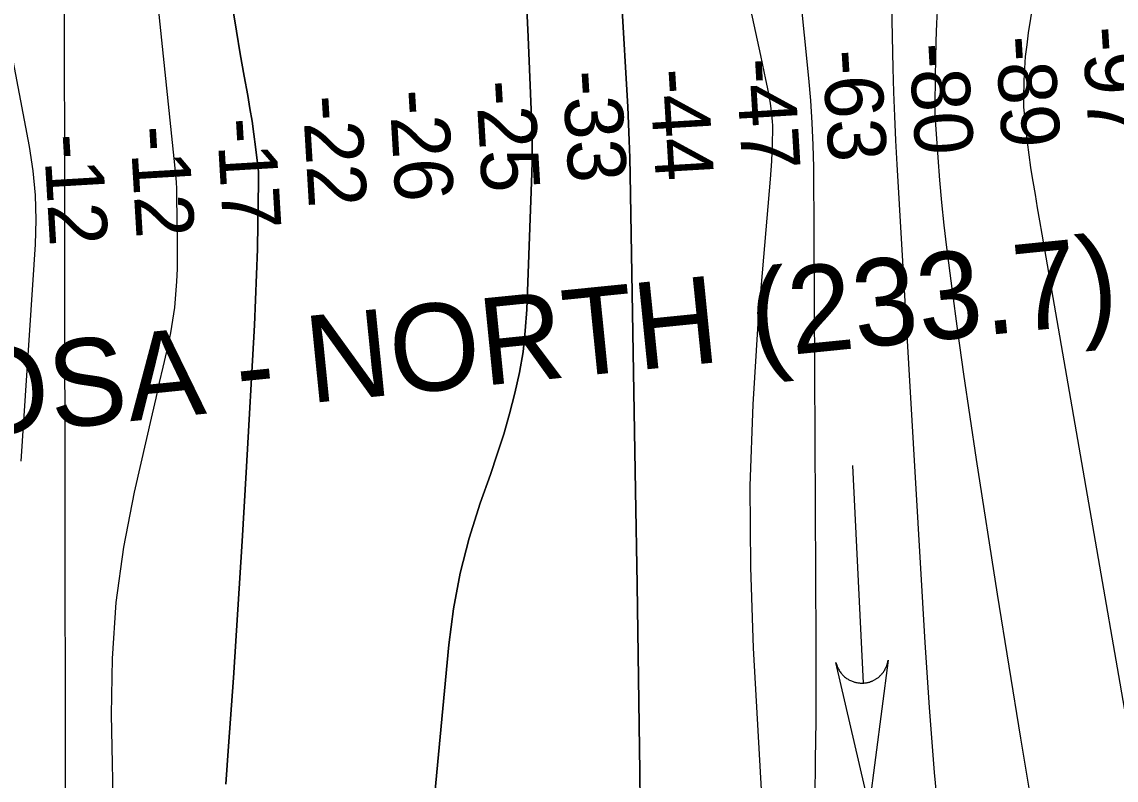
# Model space of a CAD drawing. Extents: x 3313442 to 3351311, y 721974 to 747360.
# Drawn here: x 3322775 to 3324032, y 728448 to 729320 of the extents above; entities that cross this region are included whole.
import ezdxf

# ---------------------------------------------------------------- set-up
doc = ezdxf.new("R2010")
doc.units = 0
for name, color, linetype in [('V-CHAN-NAID', 7, 'Continuous'), ('V-GRID-MAJR', 7, 'Continuous'), ('V-RIVR-RANG', 7, 'Continuous'), ('V-STRM-FLOW', 7, 'Continuous'), ('V-TOPO-DPTH', 7, 'Continuous'), ('V-TOPO-MAJR', 7, 'Continuous'), ('V-TOPO-MINR', 7, 'Continuous')]:
    doc.layers.add(name, color=color, linetype=linetype)

msp = doc.modelspace()

# ---------------------------------------------------------------- linework, layer by layer
at = {"layer": 'V-GRID-MAJR'}
msp.add_spline([(3322826, 727358.6), (3322818.9, 733418.5), (3322811.9, 739480.2), (3322804.8, 745542), (3322804.8, 745543.9)], degree=3, dxfattribs=at)
at = {"layer": 'V-STRM-FLOW'}
msp.add_line((3323729.4, 728810.1), (3323741.5, 728560), dxfattribs=at)
msp.add_lwpolyline([(3323770.2, 728586.4), (3323748.3, 728418.5), (3323710.3, 728583.5), (3323711.2, 728580.6), (3323712.2, 728577.8), (3323712.8, 728576.8), (3323713.2, 728575.8), (3323713.9, 728574.7), (3323714.5, 728573.7), (3323715.1, 728572.8), (3323716, 728571.7), (3323717, 728570.5), (3323717.5, 728569.8), (3323718.3, 728569), (3323719.4, 728568), (3323720.2, 728567.2), (3323721.2, 728566.4), (3323721.8, 728565.9), (3323722.5, 728565.4), (3323723.5, 728564.8), (3323724.3, 728564.3), (3323725.2, 728563.8), (3323725.9, 728563.4), (3323727, 728562.8), (3323728.1, 728562.4), (3323728.9, 728562), (3323730, 728561.6), (3323730.9, 728561.3), (3323731.7, 728561.1), (3323732.3, 728560.9), (3323733.3, 728560.7), (3323734.3, 728560.5), (3323735.3, 728560.3), (3323736.2, 728560.2), (3323737.2, 728560.1), (3323738.2, 728560), (3323739, 728559.9), (3323740.2, 728559.9), (3323741.5, 728560), (3323741.9, 728560), (3323742.5, 728560), (3323743.3, 728560.1), (3323744, 728560.2), (3323744.6, 728560.3), (3323745.3, 728560.4), (3323746.1, 728560.5), (3323746.6, 728560.6), (3323747.4, 728560.8), (3323748.2, 728561), (3323748.7, 728561.2), (3323749.9, 728561.6), (3323750.6, 728561.8), (3323751.1, 728562), (3323751.8, 728562.3), (3323752.5, 728562.6), (3323753.2, 728562.9), (3323754, 728563.3), (3323754.7, 728563.7), (3323755.3, 728564), (3323755.8, 728564.3), (3323756.4, 728564.7), (3323757, 728565.1), (3323757.7, 728565.5), (3323758.3, 728566), (3323759, 728566.5), (3323759.8, 728567.2), (3323760.3, 728567.7), (3323760.9, 728568.2), (3323761.5, 728568.8), (3323762, 728569.2), (3323762.4, 728569.7), (3323763.1, 728570.5), (3323763.2, 728570.6), (3323763.6, 728571), (3323763.9, 728571.4), (3323764.3, 728571.9), (3323764.8, 728572.6), (3323765.2, 728573.2), (3323765.5, 728573.7), (3323765.9, 728574.4), (3323766.3, 728575), (3323766.6, 728575.5), (3323766.9, 728576.1), (3323767.4, 728577), (3323767.6, 728577.5), (3323767.8, 728577.9), (3323768, 728578.3), (3323768.2, 728578.7), (3323768.4, 728579.3), (3323768.7, 728580), (3323768.9, 728580.6), (3323769.1, 728581.2), (3323769.3, 728582), (3323769.5, 728582.4), (3323769.7, 728583.2), (3323769.9, 728584.1), (3323770, 728584.8), (3323770.1, 728585.3), (3323770.2, 728585.8), (3323770.2, 728586.1)], close=True, dxfattribs=at)
at = {"layer": 'V-TOPO-DPTH'}
for points in [[(3323353.4, 729367.6), (3323356.6, 729302.9), (3323360.6, 729200.5), (3323361, 729186.9), (3323361.1, 729173.3), (3323361, 729159.8), (3323360.6, 729146.2), (3323354.9, 728989.3), (3323353.2, 728965), (3323350.6, 728940.9), (3323346.4, 728917), (3323341.3, 728893.2), (3323335.1, 728869.6), (3323328.4, 728846.2), (3323321, 728823), (3323313.2, 728799.9), (3323301.3, 728766.7), (3323288.7, 728726.7), (3323278.2, 728686.3), (3323270.7, 728645.3), (3323265.2, 728603.8), (3323219.8, 728119.9)], [(3323219.8, 728119.9), (3323265.2, 728603.8), (3323270.7, 728645.3), (3323278.2, 728686.3), (3323288.7, 728726.7), (3323301.3, 728766.7), (3323313.2, 728799.9), (3323321, 728823), (3323328.4, 728846.2), (3323335.1, 728869.6), (3323341.3, 728893.2), (3323346.4, 728917), (3323350.6, 728940.9), (3323353.2, 728965), (3323354.9, 728989.3), (3323360.6, 729146.2), (3323361, 729159.8), (3323361.1, 729173.3), (3323361, 729186.9), (3323360.6, 729200.5), (3323356.6, 729302.9), (3323353.4, 729367.6)], [(3323463.9, 729347.1), (3323470.9, 729222.6), (3323471.9, 729203.1), (3323472.7, 729183.6), (3323473.3, 729164), (3323473.8, 729144.5), (3323479.9, 728781.2), (3323481.6, 728673.4), (3323483.2, 728565.6), (3323484.7, 728457.8), (3323486.1, 728349.9)], [(3323486.1, 728349.9), (3323484.7, 728457.8), (3323483.2, 728565.6), (3323481.6, 728673.4), (3323479.9, 728781.2), (3323473.8, 729144.5), (3323473.3, 729164), (3323472.7, 729183.6), (3323471.9, 729203.1), (3323470.9, 729222.6), (3323463.9, 729347.1)], [(3323009.1, 728443.9), (3323012.2, 728487.3), (3323017.7, 728566), (3323022.9, 728644.6), (3323027.7, 728723.3), (3323032.3, 728802), (3323041.8, 728971.4), (3323043.2, 729000.6), (3323044.4, 729029.8), (3323045.3, 729059), (3323045.9, 729088.3), (3323046.7, 729135.5), (3323046.7, 729141.1), (3323046.5, 729146.7), (3323046.1, 729152.3), (3323045.5, 729157.8), (3323043.2, 729176.4), (3323041.2, 729191.2), (3323039.1, 729206), (3323036.7, 729220.7), (3323034.1, 729235.4), (3323030, 729257.6), (3323025.4, 729283.4), (3323021.1, 729309.3), (3323017, 729335.1)], [(3323009.1, 728443.9), (3323012.2, 728487.3), (3323017.7, 728566), (3323022.9, 728644.6), (3323027.7, 728723.3), (3323032.3, 728802), (3323041.8, 728971.4), (3323043.2, 729000.6), (3323044.4, 729029.8), (3323045.3, 729059), (3323045.9, 729088.3), (3323046.7, 729135.5), (3323046.7, 729141.1), (3323046.5, 729146.7), (3323046.1, 729152.3), (3323045.5, 729157.8), (3323043.2, 729176.4), (3323041.2, 729191.2), (3323039.1, 729206), (3323036.7, 729220.7), (3323034.1, 729235.4), (3323030, 729257.6), (3323025.4, 729283.4), (3323021.1, 729309.3), (3323017, 729335.1)]]:
    msp.add_lwpolyline(points, dxfattribs=at)
at = {"layer": 'V-TOPO-MAJR'}
msp.add_lwpolyline([(3323514.4, 729784.4), (3323623.4, 729281.6), (3323625.4, 729272.4), (3323627.3, 729263.3), (3323629.2, 729254.1), (3323631.1, 729245), (3323632.3, 729239.2), (3323633.5, 729232.9), (3323634.6, 729226.6), (3323635.5, 729220.3), (3323636.2, 729213.9), (3323637.1, 729205.6), (3323637.4, 729201.2), (3323637.4, 729199.1), (3323637.4, 729196.9), (3323637, 729180.6), (3323636.6, 729170.3), (3323636.2, 729160), (3323635.5, 729149.7), (3323634.7, 729139.4), (3323620.6, 728973.4), (3323614.7, 728880.1), (3323611.4, 728786.8), (3323612.1, 728693.4), (3323615.3, 728600), (3323636.6, 728220.8)], dxfattribs=at)
at = {"layer": 'V-TOPO-MINR'}
for points in [[(3322895.3, 729682.2), (3322950.4, 729151.9), (3322951.1, 729144), (3322951.7, 729136), (3322952.1, 729128.1), (3322952.3, 729120.2), (3322953.2, 729066.1), (3322953.2, 729051.2), (3322953, 729036.3), (3322952.3, 729021.5), (3322951.3, 729006.7), (3322949.8, 728991.9), (3322947.8, 728977.2), (3322945.3, 728962.6), (3322942.3, 728948.1), (3322940.7, 728941.2), (3322936.6, 728923.3), (3322932.5, 728905.4), (3322928.4, 728887.5), (3322924.3, 728869.6), (3322903.5, 728779.4), (3322891.4, 728716.1), (3322882.5, 728652.5), (3322878.3, 728588.4), (3322877.2, 728524), (3322885.3, 728128.4)], [(3323830.8, 728382.2), (3323823.7, 728457), (3323817.9, 728531.8), (3323812.8, 728606.8), (3323780.6, 729156.3), (3323779.1, 729183.9), (3323777.9, 729211.6), (3323776.9, 729239.3), (3323776.2, 729266.9), (3323768, 729650.7)], [(3323957.5, 729470.6), (3323931.4, 729307.5), (3323929.5, 729293.9), (3323927.9, 729280.2), (3323926.9, 729266.5), (3323926.3, 729252.7), (3323925.7, 729231.8), (3323925.7, 729228.5), (3323925.8, 729225.2), (3323925.9, 729222), (3323926.2, 729218.7), (3323928.4, 729196.2), (3323930, 729181.7), (3323931.8, 729167.3), (3323933.9, 729152.9), (3323936.2, 729138.5), (3323936.4, 729136.8), (3323939.1, 729121.6), (3323941.7, 729106.5), (3323944.3, 729091.3), (3323946.9, 729076.1), (3324101.5, 728187.1)], [(3323353.4, 729367.6), (3323356.6, 729302.9), (3323360.6, 729200.5), (3323361, 729186.9), (3323361.1, 729173.3), (3323361, 729159.8), (3323360.6, 729146.2), (3323354.9, 728989.3), (3323353.2, 728965), (3323350.6, 728940.9), (3323346.4, 728917), (3323341.3, 728893.2), (3323335.1, 728869.6), (3323328.4, 728846.2), (3323321, 728823), (3323313.2, 728799.9), (3323301.3, 728766.7), (3323288.7, 728726.7), (3323278.2, 728686.3), (3323270.7, 728645.3), (3323265.2, 728603.8), (3323219.8, 728119.9)], [(3323686.2, 728427.1), (3323686.9, 728471.7), (3323687.5, 728516.4), (3323687.7, 728561.1), (3323687.6, 728605.7), (3323684.7, 729153), (3323684.1, 729178.6), (3323683.1, 729204.2), (3323681.4, 729229.8), (3323679.1, 729255.4), (3323669, 729354.6)], [(3323486.1, 728349.9), (3323484.7, 728457.8), (3323483.2, 728565.6), (3323481.6, 728673.4), (3323479.9, 728781.2), (3323473.8, 729144.5), (3323473.3, 729164), (3323472.7, 729183.6), (3323471.9, 729203.1), (3323470.9, 729222.6), (3323463.9, 729347.1)], [(3323017, 729335.1), (3323021.1, 729309.3), (3323025.4, 729283.4), (3323030, 729257.6), (3323034.1, 729235.4), (3323036.7, 729220.7), (3323039.1, 729206), (3323041.2, 729191.2), (3323043.2, 729176.4), (3323045.5, 729157.8), (3323046.1, 729152.3), (3323046.5, 729146.7), (3323046.7, 729141.1), (3323046.7, 729135.5), (3323045.9, 729088.3), (3323045.3, 729059), (3323044.4, 729029.8), (3323043.2, 729000.6), (3323041.8, 728971.4), (3323032.3, 728802), (3323027.7, 728723.3), (3323022.9, 728644.6), (3323017.7, 728566), (3323012.2, 728487.3), (3323009.1, 728443.9)], [(3323936.5, 728414), (3323922.6, 728496.7), (3323909.2, 728579.4), (3323896, 728662.3), (3323872, 728816.9), (3323864.5, 728866.1), (3323857.3, 728915.3), (3323850.4, 728964.5), (3323843.8, 729013.8), (3323837.7, 729060.9), (3323834.6, 729086.6), (3323831.8, 729112.4), (3323829.5, 729138.2), (3323827.6, 729164.1), (3323824.8, 729207.6), (3323824.5, 729211.7), (3323824.4, 729215.9), (3323824.3, 729220), (3323824.3, 729224.2), (3323824.6, 729257), (3323824.9, 729277.6), (3323825.4, 729298.1), (3323826.3, 729318.7), (3323827.3, 729339.2)], [(3322773.7, 728815.2), (3322790.1, 729064.3), (3322790.8, 729092.6), (3322790.2, 729120.9), (3322787.4, 729149), (3322783.3, 729177), (3322760.5, 729298.1)]]:
    msp.add_lwpolyline(points, dxfattribs=at)

# ---------------------------------------------------------------- texts
at = {"layer": 'V-CHAN-NAID'}
msp.add_text('FORMOSA - NORTH (233.7) (3)', height=100, rotation=5.7453, dxfattribs=at).set_placement((3322315, 728802.2))
at = {"layer": 'V-RIVR-RANG'}
for s, p in [('-97', (3323993.4, 729313.8)), ('-80', (3323794.3, 729294.7)), ('-89', (3323893.9, 729302.8)), ('-63', (3323694.6, 729286.9)), ('-47', (3323595.1, 729277.2)), ('-33', (3323395.7, 729263.1)), ('-44', (3323495.7, 729265.1)), ('-25', (3323296.2, 729251.8)), ('-22', (3323097, 729234.5)), ('-26', (3323196.7, 729241.1)), ('-17', (3322998.4, 729208.5)), ('-12', (3322898.8, 729199.4)), ('-12', (3322799.3, 729190.2))]:
    msp.add_text(s, height=67, rotation=273.3981, dxfattribs=at).set_placement(p)

doc.saveas('drawing.dxf')
